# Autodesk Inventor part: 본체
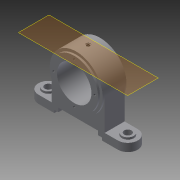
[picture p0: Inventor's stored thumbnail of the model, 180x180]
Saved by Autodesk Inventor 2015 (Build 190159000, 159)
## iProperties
Created: 2019-05
Part Number: 본체
Material: 일반
Document SubType Name: Modeling
Designer: now
Density: 1 g/cm^3
Appearance: 기본값
Author: now
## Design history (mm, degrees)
sketch "스케치1"
  geometry: C1 r 40 at (0, 0); 1 further point
  constraints: 1 centre point, 1 coincident
  dimensions: "d0" = 80 diameter of C1
extrude "돌출1" new body sketch "스케치1" stored distance "d1" = 36; taper "d2" = 0 deg
sketch "스케치2"
  geometry: C1 r 36 at (0, 0); 1 further point
  constraints: 1 centre point, 1 coincident
  dimensions: "d3" = 72 diameter of C1
extrude "돌출2" join sketch "스케치2" distance "d4" = 3; taper "d5" = 0 deg
sketch "스케치3"
  geometry: 1 further point
hole "구멍1" sketch "스케치3" at (0, 0) diameter "d6" = 52; stored, may be unused: countersink angle "d10" = 90 deg, drill point angle "d12" = 118 deg; dims "d7" = 6, "d8" = 4, "d9" = 2, "d11" = 8
node "작업 평면1"
sketch "스케치4"
  geometry: L1 (-75, -15)-(75, -15); L2 (75, -15)-(75, 15); L3 (75, 15)-(-75, 15); L4 (-75, 15)-(-75, -15); 3 further points
  constraints: 8 end point, 2 midpoint, 2 parallel, 1 horizontal, 1 horizontal alignment, 1 perpendicular, 1 vertical alignment
  dimensions: "d14" = 150 distance between parallel lines of L4 L2; "d15" = 30 distance between parallel lines of L3 L1
extrude "돌출3" join sketch "스케치4" distance "d16" = 12; taper "d17" = 0 deg
fillet "모깎기1" dims "d18" = 15
sketch "스케치5"
  geometry: L1 (60, -15)-(-60, -15) reference; L2 (-60, 15)-(60, 15) reference; C1 r 9 at (60, 0); A1 r 15 centre (60, 0) between (60, -15) and (60, 15) reference; A2 r 15 centre (-60, 0) between (-60, 15) and (-60, -15) reference; 1 further point
  constraints: 1 centre point, 1 coincident
  dimensions: "d19" = 18 diameter of C1
extrude "돌출4" join sketch "스케치5" distance "d20" = 3; taper "d21" = 0 deg
sketch "스케치6"
  geometry: C1 r 9 at (0, 0) reference; 1 further point
hole "구멍2" sketch "스케치6" at (0, 0) diameter "d22" = 11; stored, may be unused: countersink angle "d26" = 90 deg, drill point angle "d28" = 118 deg; dims "d23" = 6, "d24" = 4, "d25" = 2, "d27" = 8
sketch "스케치7"
  geometry: L1 (60, -15)-(-60, -15) reference; L2 (-60, 15)-(60, 15) reference; L3 (40, -15)-(-40, -15); L4 (-40, -15)-(-40, 15); L5 (-40, 15)-(40, 15); L6 (40, 15)-(40, -15); L7 (40, -15)-(-40, 15); L8 (-40, -15)-(40, 15); C1 r 5.5 at (-60, 0) reference; C2 r 9 at (-60, 0) reference; C3 r 5.5 at (60, 0) reference; C4 r 9 at (60, 0) reference; A1 r 15 centre (60, 0) between (60, -15) and (60, 15) reference; A2 r 15 centre (-60, 0) between (-60, 15) and (-60, -15) reference; 1 further point
  constraints: 12 end point, 2 midpoint, 2 parallel, 1 horizontal, 1 perpendicular, 1 point on line
  dimensions: "d29" = 40 distance from line of point (0, 0) L4
extrude "돌출5" join sketch "스케치7" stored distance "d30" = 3; taper "d31" = 0 deg
sketch "스케치8"
  geometry: L1 (100, 60)-(100, 12) reference; L2 (100, 12)-(120, 12) reference; L3 (120, 0)-(120, 12) reference; L4 (120, 0)-(0, 0) reference; L5 (0, 0)-(0, 12) reference; L6 (0, 12)-(20, 12) reference; L7 (20, 12)-(20, 60) reference; L8 (24, 0)-(96, 0); L9 (96, 0)-(96, 4); L10 (96, 4)-(24, 4); L11 (24, 4)-(24, 0); C1 r 26 at (60, 60) reference; A1 r 40 centre (60, 60) between (100, 60) and (20, 60) reference; A2 r 40 centre (60, 60) between (20, 60) and (100, 60) reference; 2 further points
  constraints: 8 end point, 2 parallel, 1 horizontal, 1 midpoint, 1 perpendicular, 1 point on line, 1 vertical alignment
  dimensions: "d32" = 4 distance between parallel lines of L4 L10; "d33" = 72 distance between parallel lines of L9 L11
extrude "돌출6" cut sketch "스케치8" stored distance "d34" = 3; taper "d35" = 0 deg
sketch "스케치9"
  geometry: L1 (-20, 60)-(-20, 12) reference; L2 (-20, 12)-(0, 12) reference; L3 (0, 0)-(0, 12) reference; L4 (0, 0)-(-24, 0) reference; L5 (-24, 0)-(-24, 4) reference; L6 (-24, 4)-(-96, 4) reference; L7 (-96, 4)-(-96, 0) reference; L8 (-96, 0)-(-120, 0) reference; L9 (-120, 0)-(-120, 12) reference; L10 (-120, 12)-(-100, 12) reference; L11 (-100, 12)-(-100, 60) reference; L12 (-90, 4)-(-30, 4); L13 (-30, 4)-(-30, 10); L14 (-30, 10)-(-90, 10); L15 (-90, 10)-(-90, 4); C1 r 26 at (-60, 60) reference; A1 r 40 centre (-60, 60) between (-20, 60) and (-100, 60) reference; A2 r 40 centre (-60, 60) between (-100, 60) and (-20, 60) reference; 2 further points
  constraints: 8 end point, 2 parallel, 1 horizontal, 1 midpoint, 1 perpendicular, 1 point on line, 1 vertical alignment
  dimensions: "d36" = 6 distance between parallel lines of L12 L14; "d37" = 60 distance between parallel lines of L13 L15
extrude "돌출7" cut sketch "스케치9" stored distance "d38" = 3; taper "d39" = 0 deg
sketch "스케치10"
  geometry: 2 further points
  constraints: 1 vertical alignment
  dimensions: "d40" = 31 distance of point (0, 0) point (0, 31)
hole "구멍3" sketch "스케치10" at (0, 31) diameter "d41" = 3.242; stored, may be unused: countersink angle "d45" = 90 deg, drill point angle "d47" = 118 deg; dims "d42" = 6, "d43" = 4, "d44" = 2, "d46" = 8
node "작업 평면2"
sketch "스케치11"
  geometry: 1 further point
hole "구멍4" sketch "스케치11" at (0, 0) diameter "d52" = 4.917; stored, may be unused: countersink angle "d56" = 90 deg, drill point angle "d58" = 118 deg; dims "d53" = 8, "d54" = 7, "d55" = 1, "d57" = 10
node "솔리드1"
mirror "대칭1"
mirror "대칭2"
pattern_circular "원형 패턴1" dims angle "d49" = 360 deg
mirror "대칭3"
node "절단 모서리 투영1"
node "절단 모서리 투영2"
node "절단 모서리 투영3"
node "절단 모서리 투영4"
node "절단 모서리 투영5"
